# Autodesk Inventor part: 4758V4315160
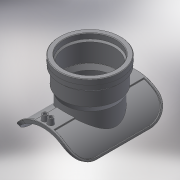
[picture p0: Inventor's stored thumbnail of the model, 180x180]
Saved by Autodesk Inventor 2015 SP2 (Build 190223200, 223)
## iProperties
Created: 2017-08
Part Number: 4758V4315160
Material: Generic
Description: PLASSON WASTEWATER SADDLE 280-315X160 PVC/PP ADAPTOR INLET
Document SubType Name: Modeling
Designer: Кирилл
Density: 1 g/cm^3
Appearance: Default
Author: Кирилл
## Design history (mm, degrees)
derived "4758V4.ipt"
feature "Solid1::4758V4.ipt"
feature "Solid2::4758V4.ipt"
feature "Solid3::4758V4.ipt"
tag "TaggingFeature1"
body "Solid1"
other parameters: "d0" = 315, "d1" = 245, "d2" = 343.35, "d4" = 0, "d5" = 73.5, "d6" = 9.6, "d7" = 30 deg, "d8" = 15 deg, "d10" = 0, "d11" = 204.75, "d38" = 1.575, "d40" = 183.5, "d41" = 15, "d42" = 130.5, "d43" = 17.6, "d44" = 8.8, "d46" = 5 deg, "d47" = 4, "d49" = 4, "d51" = 14, "d52" = 0, "d53" = 3, "d54" = 0, "d57" = 0.5, "d59" = 16, "d60" = 5.6, "d61" = 40 deg, "d62" = 152, "d63" = 156.8, "d64" = 144, "d65" = 155 deg, "d66" = 125, "d68" = 188.1, "d69" = 45 deg, "d70" = 175, "d72" = 7.5, "d75" = 0, "d77" = 0, "d78" = 1.6, "d81" = 37.5, "d_" = 315, "B_" = 245, "H_" = 125, "d71" = 7.5
